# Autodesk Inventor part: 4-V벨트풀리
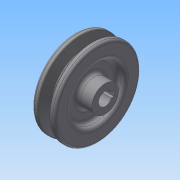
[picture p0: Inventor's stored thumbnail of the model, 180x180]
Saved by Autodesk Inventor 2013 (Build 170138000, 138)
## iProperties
Created: 2015-02
Part Number: 4-V벨트풀리
Material: 일반
Document SubType Name: Modeling
Designer: Administrator
Density: 1 g/cm^3
Author: Administrator
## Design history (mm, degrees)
sketch "스케치1"
  geometry: L1 (0, 0)-(-25, 0); L2 (-25, 5.5)-(0, 5.5); L3 (0, 5.5)-(0, 11); L4 (0, 11)-(-12, 11); L5 (-12, 11)-(-12, 22); L6 (-12, 22)-(-6, 22); L7 (-6, 22)-(-6, 35.2); L8 (-6, 35.2)-(-10.675, 35.2); L9 (-10.675, 35.2)-(-13.426, 26.2); L10 (-13.426, 26.2)-(-17.574, 26.2); L11 (-17.574, 26.2)-(-20.325, 35.2); L12 (-20.325, 35.2)-(-25, 35.2); L13 (-25, 35.2)-(-25, 22); L14 (-25, 22)-(-19, 22); L15 (-19, 22)-(-19, 11); L16 (-19, 11)-(-25, 11); L17 (-25, 11)-(-25, 5.5); 2 further points
  constraints: 34 end point, 13 parallel, 3 equal length, 3 vertical alignment, 2 collinear, 2 horizontal alignment, 2 point on line, 1 horizontal, 1 perpendicular
  dimensions: "d0" = 25 distance of L1.start L1.end; "d1" = 6 distance of L13.end L14.end; "d2" = 11 diameter of L2 L1; "d3" = 22 diameter of L4 L1; "d4" = 44 diameter of L14 L1; "d5" = 8 distance of point (-11.5, 32.5) point (-19.5, 32.5); "d6" = 34 deg angle of L9 L11; "d7" = 19 distance between parallel lines of L7 L13; "d8" = 2.7 distance from line of L12 point (-19.5, 32.5); "d9" = 6.3 distance from line of point (-19.5, 32.5) L10; "d10" = 65 diameter of point (-19.5, 32.5) L1
revolve "회전1" sketch "스케치1" stored, may be unused: angle "d11" = 90 deg
sketch "스케치2"
  geometry: L1 (-2, 5.123)-(-2, 7.3); L2 (-2, 7.3)-(2, 7.3); L3 (2, 7.3)-(2, 5.123); C1 r 11 at (0, 0) reference; A1 r 5.5 centre (0, 0) between (-2, 5.123) and (2, 5.123) reference; 1 further point
  constraints: 6 end point, 2 point on circle, 1 midpoint, 1 parallel, 1 perpendicular, 1 vertical, 1 vertical alignment
  dimensions: "d12" = 4 distance of L1.end L2.end; "d14" = 12.8 dimension on A1 L2
extrude "돌출1" cut sketch "스케치2" stored distance "d15" = 10; taper "d16" = 0 deg
fillet "모깎기1" dims "d17" = 2, "d18" = 1, "d19" = 0.5
fillet "모깎기2" dims "d20" = 3
node "솔리드1"
